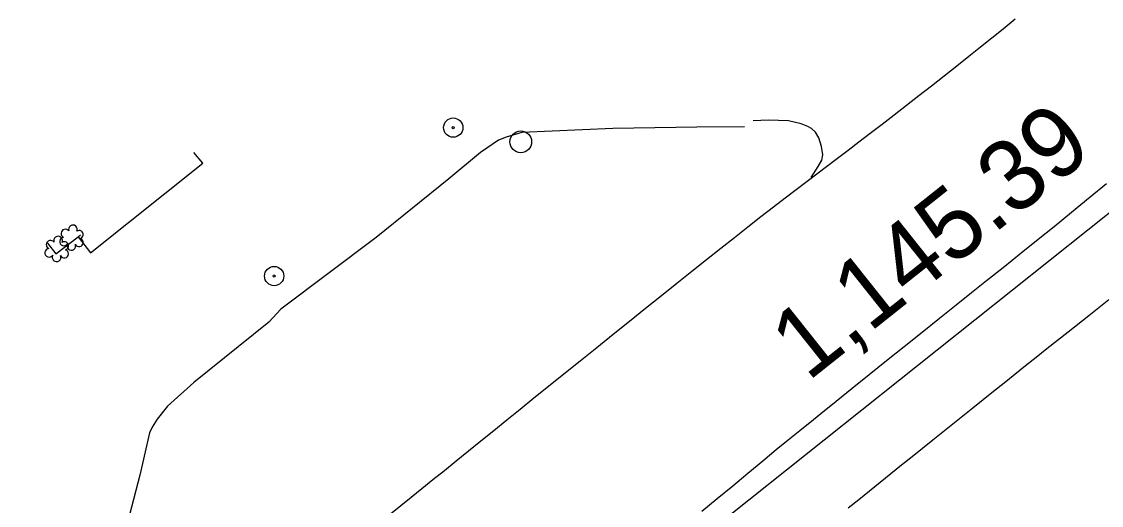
# Model space of a CAD drawing. Extents: x 471894 to 476235, y 503501 to 507878.
# Drawn here: x 473682.4 to 473926.8, y 506381.3 to 506490.8 of the extents above; entities that cross this region are included whole.
import ezdxf

# ---------------------------------------------------------------- set-up
doc = ezdxf.new("R2010")
doc.units = 0
for name, color, linetype in [('Exist Horizontal Alignment', 7, 'Continuous'), ('Exist Horizontal Alignment Direction Label', 7, 'Continuous'), ('Exist Other Culture Area Outline', 7, 'Continuous'), ('Exist Other Culture Sign Post CELL', 7, 'Continuous'), ('Exist Roads Curbs', 7, 'Continuous'), ('Exist Roads EOP', 7, 'Continuous'), ('Exist Roads EOP Other', 7, 'Continuous'), ('Exist Utilities Other Located Object CELL', 7, 'Continuous'), ('Exist Utilities Other Pole CELL', 7, 'Continuous'), ('Exist Vegetation Shrub CELL', 7, 'Continuous')]:
    doc.layers.add(name, color=color, linetype=linetype)

msp = doc.modelspace()

# ---------------------------------------------------------------- linework, layer by layer
at = {"layer": 'Exist Horizontal Alignment'}
msp.add_line((473294.53, 505943.19), (474190.95, 506656.19), dxfattribs=at)
at = {"layer": 'Exist Other Culture Area Outline'}
msp.add_line((473695.22, 506442.08), (473695.74, 506442.52), dxfattribs=at)
at = {"layer": 'Exist Other Culture Sign Post CELL'}
for radius in [2.18, 0.24]:
    msp.add_circle((473739.59, 506433.21), radius, dxfattribs=at)
at = {"layer": 'Exist Roads Curbs'}
msp.add_lwpolyline([(473846.01, 506466.97), (473835.23, 506466.87), (473816.22, 506466.61), (473795.62, 506465.73), (473792.07, 506464.67), (473790.34, 506463.97), (473786.26, 506461.18), (473779.12, 506455.22), (473762.64, 506441.9), (473741.1, 506425.73), (473738.35, 506422.75), (473721.38, 506409.13), (473715.44, 506403.75), (473713.1, 506400.83), (473712, 506399.01), (473711.41, 506397.72), (473709.21, 506388.16), (473706.82, 506379.16)], dxfattribs=at)
at = {"layer": 'Exist Roads EOP'}
for points in [[(473765.95, 506379.41), (473770.59, 506383.17), (473773.02, 506385.13), (473775.52, 506387.15), (473778.11, 506389.24), (473780.79, 506391.41), (473783.55, 506393.64), (473786.38, 506395.93), (473789.27, 506398.27), (473792.22, 506400.66), (473795.24, 506403.1), (473798.37, 506405.64), (473801.68, 506408.31), (473805.17, 506411.11), (473808.85, 506414.06), (473812.59, 506417.06), (473816.31, 506420.04), (473819.99, 506423), (473823.65, 506425.94), (473827.24, 506428.83), (473830.73, 506431.63), (473834.13, 506434.34), (473837.42, 506436.97), (473840.63, 506439.51), (473843.75, 506441.97), (473846.79, 506444.36), (473849.74, 506446.66), (473852.58, 506448.86), (473855.24, 506450.91), (473857.74, 506452.83), (473862.35, 506456.33), (473867.03, 506459.87), (473869.44, 506461.69), (473871.92, 506463.56), (473874.48, 506465.52), (473877.13, 506467.56), (473879.87, 506469.67), (473882.67, 506471.85), (473885.49, 506474.05), (473888.34, 506476.28), (473891.22, 506478.55), (473894.06, 506480.79), (473896.8, 506482.97), (473899.44, 506485.08), (473901.97, 506487.12), (473904.53, 506489.18), (473907.25, 506491.38)], [(473927.92, 506454.1), (473924.26, 506451.05), (473920.02, 506447.56), (473916.06, 506444.36), (473912.43, 506441.46), (473908.58, 506438.38), (473904.51, 506435.11), (473900.77, 506432.12), (473897.39, 506429.42), (473893.88, 506426.6), (473890.15, 506423.6), (473886.22, 506420.47), (473882.14, 506417.23), (473878.13, 506414.02), (473874.21, 506410.85), (473870.41, 506407.78), (473866.74, 506404.81), (473863.26, 506402.01), (473861.59, 506400.67), (473858.52, 506398.19), (473855.86, 506396.05), (473853.2, 506393.88), (473850.13, 506391.33), (473846.8, 506388.56), (473843.36, 506385.69), (473839.86, 506382.79), (473836.38, 506379.94)], [(473869.5, 506380.77), (473871.88, 506382.68), (473874.29, 506384.61), (473876.72, 506386.57), (473879.16, 506388.53), (473881.56, 506390.46), (473883.94, 506392.37), (473888.61, 506396.12), (473893.17, 506399.78), (473897.66, 506403.4), (473902.33, 506407.14), (473904.74, 506409.06), (473907.18, 506411), (473909.61, 506412.94), (473912.04, 506414.87), (473914.46, 506416.8), (473916.87, 506418.71), (473919.24, 506420.6), (473923.9, 506424.31), (473928.45, 506427.93)]]:
    msp.add_lwpolyline(points, dxfattribs=at)
at = {"layer": 'Exist Roads EOP Other'}
for points in [[(473861.1, 506455.53), (473862.72, 506458.02), (473863.51, 506459.47), (473863.72, 506460.61), (473863.47, 506462.53), (473862.8, 506464.51), (473862.1, 506465.74), (473861.17, 506466.61), (473860.38, 506467.09), (473858.83, 506467.64), (473855.97, 506468.36), (473851.47, 506468.45), (473847.97, 506468.36)], [(473688.31, 506440.63), (473690.21, 506438.24), (473695.22, 506442.08), (473698, 506438.43), (473723.47, 506458.78), (473721.39, 506461.15)]]:
    msp.add_lwpolyline(points, dxfattribs=at)
at = {"layer": 'Exist Utilities Other Located Object CELL'}
for radius in [2.18, 0.24]:
    msp.add_circle((473780.11, 506466.8), radius, dxfattribs=at)
at = {"layer": 'Exist Utilities Other Pole CELL'}
msp.add_circle((473795.39, 506463.59), 2.46, dxfattribs=at)
at = {"layer": 'Exist Vegetation Shrub CELL'}
for p, q in [((473693.82, 506441.73), (473693.82, 506441.73)), ((473690.48, 506439.18), (473690.48, 506439.18))]:
    msp.add_line(p, q, dxfattribs=at)
for centre, radius, start, end in [((473692.34, 506442.85), 0.968, 35.8908, 245.4216), ((473694.05, 506443.77), 0.99, 334.8391, 200.4717), ((473695.49, 506442.6), 0.929, 284.4567, 126.0861), ((473688.99, 506440.3), 0.968, 35.8908, 245.4216), ((473690.7, 506441.22), 0.99, 334.8391, 200.4717), ((473692.02, 506441.02), 0.955, 95.1099, 327.9534), ((473692.15, 506440.05), 0.929, 284.4567, 126.0861), ((473695.46, 506440.8), 0.937, 204.9913, 73.4601), ((473688.67, 506438.47), 0.955, 95.1099, 327.9534), ((473692.11, 506438.25), 0.937, 204.9913, 73.4601), ((473693.69, 506440.04), 0.984, 151.2797, 21.387), ((473690.35, 506437.49), 0.984, 151.2797, 21.387)]:
    msp.add_arc(centre, radius, start, end, dxfattribs=at)

# ---------------------------------------------------------------- texts
at = {"layer": 'Exist Horizontal Alignment Direction Label'}
msp.add_text('1,145.39', height=16, rotation=38.4983, dxfattribs=at).set_placement((473860.31, 506409.17))

doc.saveas('drawing.dxf')
